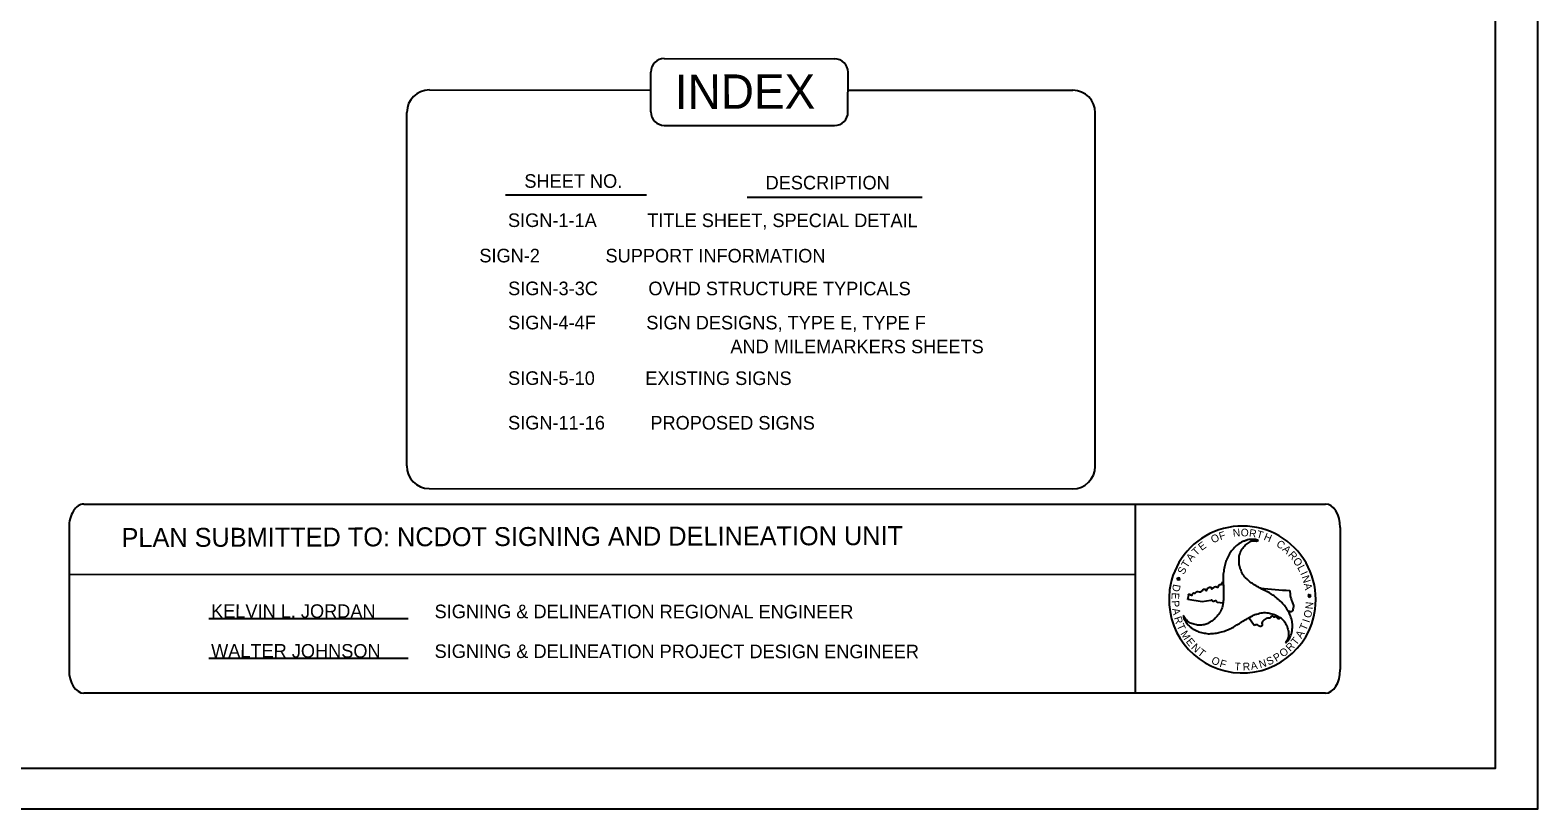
# Model space of a CAD drawing. Extents: x 49201 to 52602, y 49383 to 50479.
# Drawn here: x 51649 to 52386, y 49383 to 49764 of the extents above; entities that cross this region are included whole.
import ezdxf

# ---------------------------------------------------------------- set-up
doc = ezdxf.new("R2010")
doc.units = 0
for name, color, linetype in [('Default', 7, 'Continuous'), ('Old_Level_18', 7, 'Continuous'), ('Sheet Plot Border Outside CELL', 7, 'Continuous'), ('Sheet Title CELL', 7, 'Continuous')]:
    doc.layers.add(name, color=color, linetype=linetype)

msp = doc.modelspace()

# ---------------------------------------------------------------- linework, layer by layer
at = {"layer": 'Default'}
for p, q in [((51881.55, 49683.22), (51950.37, 49683.19)), ((51999.63, 49682.07), (52085.13, 49682.03)), ((51675.33, 49532.2), (52282.25, 49532.19)), ((52189.19, 49532.19), (52189.2, 49439.85)), ((51668.14, 49520.72), (51668.13, 49451.35)), ((52289.45, 49520.71), (52289.46, 49451.34)), ((51668.13, 49497.85), (52189.19, 49497.98)), ((51736.51, 49476.39), (51833.86, 49476.31)), ((51736.5, 49456.97), (51833.85, 49456.9)), ((52282.26, 49439.85), (51675.33, 49439.85))]:
    msp.add_line(p, q, dxfattribs=at)
for centre, major_axis, start_param, end_param in [((51675.34, 49520.71), (-0.01, 11.49), 6.282483, 7.85328), ((52282.25, 49520.7), (0.01, 11.49), 4.713091, 6.283887), ((51675.33, 49451.35), (0.01, -11.49), 4.711687, 6.282483), ((52282.26, 49451.34), (-0.01, -11.49), 0.000702, 1.571498)]:
    msp.add_ellipse(centre, major_axis=major_axis, ratio=0.62659, start_param=start_param, end_param=end_param, dxfattribs=at)
at = {"layer": 'Old_Level_18'}
msp.add_lwpolyline([(52365.34, 50453.17), (50865.34, 50453.17), (50865.34, 49403.17), (52365.34, 49403.17)], close=True, dxfattribs=at)
at = {"layer": 'Sheet Plot Border Outside CELL'}
msp.add_lwpolyline([(52386.04, 50479.27), (50703.13, 50479.27), (50703.13, 49383.36), (52386.04, 49383.36)], close=True, dxfattribs=at)
at = {"layer": 'Sheet Title CELL'}
for p, q in [((51952.47, 49723.8), (51952.48, 49743.19)), ((52048.87, 49723.72), (52048.88, 49743.12)), ((51844.27, 49734.49), (51952.48, 49734.44)), ((52048.87, 49734.43), (52158.76, 49734.31)), ((51833.18, 49550.82), (51833.27, 49723.49)), ((52169.66, 49550.64), (52169.75, 49723.31)), ((51844.17, 49539.81), (52158.66, 49539.64)), ((52249.49, 49514.47), (52249.41, 49514.4)), ((52249.49, 49514.47), (52249.41, 49514.4)), ((52210.05, 49495.58), (52209.58, 49496.04)), ((52209.58, 49496.04), (52210.23, 49495.95)), ((52209.78, 49494.99), (52210.05, 49495.58)), ((52210.32, 49495.31), (52209.78, 49494.99)), ((52210.23, 49495.95), (52210.49, 49496.52)), ((52210.8, 49494.86), (52210.32, 49495.31)), ((52210.49, 49496.52), (52210.63, 49495.9)), ((52210.63, 49495.9), (52211.26, 49495.81)), ((52211.26, 49495.81), (52210.68, 49495.5)), ((52210.68, 49495.5), (52210.8, 49494.86)), ((52250.42, 49491.14), (52250.42, 49491.14)), ((52215.02, 49485.58), (52215.39, 49487.81)), ((52222.02, 49484.38), (52215.02, 49485.58)), ((52226.22, 49485.03), (52222.02, 49484.38)), ((52232.19, 49483.73), (52229.26, 49484.16)), ((52274.19, 49487.64), (52273.56, 49487.73)), ((52273.56, 49487.73), (52274.03, 49487.28)), ((52274.03, 49487.28), (52273.77, 49486.69)), ((52273.77, 49486.69), (52274.31, 49487)), ((52274.47, 49488.21), (52274.19, 49487.64)), ((52274.31, 49487), (52274.78, 49486.56)), ((52274.61, 49487.59), (52274.47, 49488.21)), ((52275.24, 49487.52), (52274.61, 49487.59)), ((52274.67, 49487.2), (52275.24, 49487.52)), ((52274.78, 49486.56), (52274.67, 49487.2)), ((52247.46, 49472.93), (52244.79, 49476.72)), ((52244.79, 49476.72), (52244.79, 49476.72))]:
    msp.add_line(p, q, dxfattribs=at)
for points in [[(51959.08, 49749.79), (52042.28, 49749.72)], [(51959.07, 49717.19), (52042.27, 49717.12)]]:
    msp.add_lwpolyline(points, dxfattribs=at)
for centre, radius, start, end in [((51959.08, 49743.19), 6.6, 89.97341, 179.97341), ((52042.28, 49743.12), 6.6, 359.97341, 89.97341), ((51844.27, 49723.49), 11, 89.97341, 179.97341), ((52158.75, 49723.31), 11, 359.97341, 89.97341), ((51959.07, 49723.79), 6.6, 179.97341, 269.97341), ((52042.27, 49723.72), 6.6, 269.97341, 359.97341), ((51844.18, 49550.81), 11, 179.97341, 269.97341), ((52158.66, 49550.64), 11, 269.97341, 359.97341), ((52241.64, 49485.59), 35.88, 352.41059, 172.41059), ((52272.67, 49687.3), 197.41, 258.08908, 258.18868), ((52272.67, 49687.3), 197.41, 263.52813, 267.73415), ((52241.64, 49485.59), 35.88, 172.41059, 352.41059)]:
    msp.add_arc(centre, radius, start, end, dxfattribs=at)
for points in [[(52249.41, 49514.4), (52248.6, 49514.73), (52246.13, 49514.96), (52243.51, 49514.49), (52243.28, 49514.4), (52241.93, 49513.91), (52240.47, 49513.09), (52238.2, 49511.46), (52236.35, 49509.32), (52235.6, 49508.4), (52234.99, 49507.23), (52233.81, 49504.72), (52233.05, 49502.25), (52232.49, 49499.31), (52232.19, 49496.71), (52232.26, 49494), (52232.37, 49491.27), (52232.41, 49488.62), (52232.41, 49485.9), (52232.07, 49483.24), (52232.03, 49483.01), (52231.18, 49480.25), (52229.71, 49477.93), (52227.95, 49476.05), (52226.96, 49475.2), (52225.59, 49474.4), (52224.81, 49473.93), (52223.01, 49473.3), (52220.39, 49473.05), (52217.92, 49473.52), (52215.8, 49474.37), (52214.03, 49475.87), (52212.73, 49477.86)], [(52262.74, 49464.38), (52263.39, 49464.9), (52264.85, 49466.93), (52265.76, 49469.43), (52265.82, 49469.68), (52266.03, 49471.09), (52266.07, 49472.78), (52265.81, 49475.56), (52264.85, 49478.22), (52264.45, 49479.33), (52263.73, 49480.47), (52262.15, 49482.73), (52260.4, 49484.63), (52258.13, 49486.57), (52256.02, 49488.11), (52253.63, 49489.44), (52251.22, 49490.7), (52248.93, 49491.98), (52246.53, 49493.35), (52244.43, 49494.97), (52244.26, 49495.13), (52242.26, 49497.26), (52240.99, 49499.7), (52240.22, 49502.14), (52240.03, 49503.41), (52240.02, 49505.01), (52239.98, 49505.94), (52240.36, 49507.79), (52241.44, 49510.21), (52243.07, 49512.09), (52244.88, 49513.49), (52247.08, 49514.27), (52249.41, 49514.4), (52249.49, 49514.47)], [(52215.39, 49487.81), (52215.34, 49488.03), (52215.75, 49488.22), (52216.74, 49487.65), (52217.33, 49488.03), (52217.36, 49488.48), (52217.84, 49488.88), (52218.54, 49488.64), (52219.3, 49489.38), (52219.91, 49489.44), (52221.16, 49489.28), (52222.85, 49490.58), (52223.49, 49490.58), (52223.59, 49490.16), (52223.96, 49490.03), (52224.77, 49491.18), (52224.95, 49491.34), (52226.18, 49491.64), (52226.46, 49491.38), (52226.47, 49490.82), (52226.63, 49490.69), (52227.05, 49490.91), (52227.65, 49491.5), (52228.67, 49491.87), (52229.75, 49491.59), (52230.05, 49492.46), (52231.44, 49493.15), (52231.78, 49493.63), (52231.91, 49494.15)], [(52232.26, 49494.07), (52232.26, 49494), (52232.37, 49491.27), (52232.41, 49488.62), (52232.41, 49485.9), (52232.18, 49483.73)], [(52264.23, 49479.77), (52263.73, 49480.47), (52262.15, 49482.73), (52260.4, 49484.63), (52258.13, 49486.57), (52256.02, 49488.11), (52253.63, 49489.44), (52251.22, 49490.7), (52250.42, 49491.14)], [(52229.26, 49484.16), (52229.05, 49484.73), (52228.5, 49484.97), (52227.67, 49484.67), (52227.09, 49484.78), (52226.52, 49485.33), (52226.22, 49485.03)], [(52264.86, 49490.04), (52265.06, 49487.49), (52265.97, 49484.4), (52266.59, 49482.7), (52266.39, 49481.33), (52265.85, 49479.73), (52264.25, 49479.77)], [(52212.73, 49477.86), (52212.89, 49476.99), (52213.92, 49474.72), (52215.62, 49472.68), (52215.81, 49472.55), (52216.93, 49471.6), (52218.36, 49470.76), (52220.91, 49469.59), (52223.67, 49469.09), (52224.84, 49468.88), (52226.22, 49468.94), (52228.92, 49469.19), (52231.44, 49469.74), (52234.28, 49470.74), (52236.66, 49471.77), (52239, 49473.2), (52241.3, 49474.67), (52243.58, 49476.01), (52245.94, 49477.37), (52248.4, 49478.42), (52248.67, 49478.48), (52251.49, 49479.14), (52254.2, 49479.02), (52256.68, 49478.47), (52257.95, 49478.02), (52259.29, 49477.2), (52260.14, 49476.78), (52261.55, 49475.53), (52263.07, 49473.39), (52263.9, 49471.04), (52264.22, 49468.75), (52263.8, 49466.47), (52262.74, 49464.38)], [(52244.79, 49476.72), (52245.94, 49477.37), (52248.4, 49478.42), (52248.67, 49478.48), (52251.49, 49479.14), (52254.2, 49479.02), (52256.68, 49478.47), (52257.95, 49478.02), (52259.29, 49477.2), (52260.08, 49476.8)], [(52260.06, 49476.79), (52259.64, 49476.19), (52259.07, 49476.22), (52258.19, 49477.13), (52256.96, 49477.05), (52256.46, 49477.44), (52256.09, 49477.5), (52255.08, 49476.53), (52253.86, 49476.42), (52251.74, 49475.26), (52251.24, 49474.49), (52251.14, 49472.69), (52250.62, 49472.4), (52250.06, 49472.56), (52248.94, 49473.18), (52247.46, 49472.93)]]:
    msp.add_spline(points, degree=3, dxfattribs=at)

# ---------------------------------------------------------------- texts
at = {"layer": 'Default'}
for s, height, rotation, p in [('INDEX', 16.783, 0.15565, (51964.27, 49725.19)), ('SHEET NO.', 6.638, 359.97341, (51890.69, 49686.68)), ('DESCRIPTION', 6.6381, 359.97341, (52008.61, 49685.89)), ('SIGN-1-1A          TITLE SHEET, SPECIAL DETAIL', 6.6381, 359.97341, (51882.69, 49667.54)), ('    SIGN-2             SUPPORT INFORMATION', 6.6381, 359.97341, (51858.83, 49650.26)), ('SIGN-3-3C          OVHD STRUCTURE TYPICALS', 6.6381, 359.97341, (51882.74, 49634.24)), ('SIGN-4-4F          SIGN DESIGNS, TYPE E, TYPE F', 6.6381, 359.97341, (51882.72, 49617.55)), (' AND MILEMARKERS SHEETS', 6.6381, 359.97341, (51988.93, 49605.89)), ('SIGN-5-10          EXISTING SIGNS', 6.6381, 359.97341, (51882.72, 49590.42)), ('SIGN-11-16         PROPOSED SIGNS', 6.6381, 359.97341, (51882.72, 49568.64)), ('PLAN SUBMITTED TO: NCDOT SIGNING AND DELINEATION UNIT', 9.2466, 0.14511, (51693.81, 49511.23)), ('KELVIN L. JORDAN', 6.6381, 359.95622, (51737.57, 49476.64)), ('SIGNING & DELINEATION REGIONAL ENGINEER', 6.6381, 359.95622, (51846.81, 49476.47)), ('WALTER JOHNSON', 6.6381, 359.95622, (51737.57, 49457.22)), ('SIGNING & DELINEATION PROJECT DESIGN ENGINEER', 6.6381, 359.95622, (51846.81, 49457.05))]:
    msp.add_text(s, height=height, rotation=rotation, dxfattribs=at).set_placement(p)
at = {"layer": 'Sheet Title CELL'}
for s, height, rotation, p in [('N', 3.73, 5.39436, (52237.13, 49516.19)), ('O', 3.74, 357.89625, (52240.77, 49516.51)), ('E', 3.72, 36.56752, (52221.73, 49509.28)), ('O', 3.74, 24.62814, (52227.24, 49512.95)), ('F', 3.74, 17.4813, (52230.84, 49514.58)), ('R', 3.73, 351.28633, (52244.71, 49516.37)), ('T', 3.74, 344.6367, (52248.25, 49515.83)), ('H', 3.73, 337.55197, (52251.76, 49514.84)), ('C', 3.72, 325.20963, (52257.87, 49511.94)), ('A', 3.75, 50.73837, (52216.64, 49503.77)), ('T', 3.72, 43.68315, (52219.08, 49506.76)), ('A', 3.73, 317.7126, (52260.92, 49509.8)), ('R', 3.73, 311.34865, (52263.76, 49507.22)), ('O', 3.74, 304.22905, (52266.11, 49504.54)), ('S', 3.73, 64.16684, (52213.09, 49497.52)), ('T', 3.74, 57.79068, (52214.65, 49500.71)), ('L', 3.72, 297.99537, (52268.35, 49501.25)), ('I', 3.74, 294.00602, (52269.8, 49498.37)), ('D', 3.73, 260.26359, (52207.83, 49493.29)), ('N', 3.73, 288.30592, (52270.52, 49496.7)), ('A', 3.73, 280.87394, (52271.64, 49493.21)), ('E', 3.72, 266.55147, (52207.14, 49489.06)), ('P', 3.73, 274.08387, (52206.97, 49485.01)), ('N', 3.73, 84.61872, (52276.01, 49480.7)), ('A', 3.73, 280.67644, (52207.26, 49481.03)), ('R', 3.73, 287.74508, (52208.12, 49476.69)), ('I', 3.74, 72.23508, (52274.36, 49474)), ('O', 3.72, 77.3707, (52275.07, 49476.3)), ('T', 3.73, 294.39561, (52209.42, 49472.78)), ('M', 3.72, 301.63065, (52211.22, 49468.95)), ('A', 3.74, 59.50074, (52270.5, 49466.29)), ('T', 3.73, 66.58517, (52272.7, 49470.13)), ('E', 3.72, 309.09743, (52213.78, 49464.95)), ('N', 3.74, 316.06897, (52216.36, 49461.85)), ('T', 3.73, 322.91097, (52219.42, 49458.96)), ('O', 3.74, 38.12481, (52261.51, 49457.15)), ('R', 3.74, 45.31391, (52265.04, 49459.96)), ('T', 3.72, 51.4137, (52267.91, 49462.94)), ('O', 3.73, 336.21465, (52226.08, 49454.59)), ('F', 3.73, 343.37988, (52230.23, 49452.82)), ('T', 3.72, 356.28911, (52237.68, 49451.12)), ('R', 3.74, 3.24573, (52241.9, 49450.89)), ('A', 3.72, 9.99886, (52246.01, 49451.18)), ('N', 3.72, 17.03049, (52250.35, 49452.01)), ('S', 3.72, 24.24097, (52254.36, 49453.33)), ('P', 3.73, 31.43282, (52258.12, 49455.04))]:
    msp.add_text(s, height=height, rotation=rotation, dxfattribs=at).set_placement(p)

doc.saveas('drawing.dxf')
